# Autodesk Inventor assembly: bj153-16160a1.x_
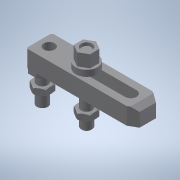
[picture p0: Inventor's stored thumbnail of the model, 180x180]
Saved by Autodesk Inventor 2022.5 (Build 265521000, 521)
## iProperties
Part Number: bj153-16160a1.x_
Material: 一般
Document SubType Name: Assembly
Designer: ImaoCorp
Sending System: SOLIDWORKS 2017-2017317
MC: AMD64
MC_MODEL: Intel64 Family 6 Model 60 Stepping 3, GenuineIntel
OS: Windows_NT
FRU: Parasolid Version 29.0, build 201,  4-17-2017
FORMAT: text
GUISE: transmit
KEY: bj153-16160a1
FILE: bj153-16160a1.x_t
DATE: Fri Mar 15 10:22:59 2019
Author: ImaoCorp
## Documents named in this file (7)
- X:\14_SW2022-Inv2022\00_全2023-1023新製品(TCC)まで\b\bj153-16160a1\BJ153-16160A1.iam
- X:\14_SW2022-Inv2022\00_全2023-1023新製品(TCC)まで\b\bj153-16160a1\bj153-16160a1_01.ipt
- X:\14_SW2022-Inv2022\00_全2023-1023新製品(TCC)まで\b\bj153-16160a1\bj153-16160a1_02.ipt
- X:\14_SW2022-Inv2022\00_全2023-1023新製品(TCC)まで\b\bj153-16160a1\bj153-16160a1_03.ipt
- X:\14_SW2022-Inv2022\00_全2023-1023新製品(TCC)まで\b\bj153-16160a1\bj153-16160a1_04.ipt
- X:\14_SW2022-Inv2022\00_全2023-1023新製品(TCC)まで\b\bj153-16160a1\bj153-16160a1_05.ipt
- X:\14_SW2022-Inv2022\00_全2023-1023新製品(TCC)まで\b\bj153-16160a1\bj153-16160a1_06.ipt
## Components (6 placed, 6 different names)
1. bj153-16160a1_01
2. bj153-16160a1_02
3. bj153-16160a1_03
4. bj153-16160a1_04
5. bj153-16160a1_05
6. bj153-16160a1_06
